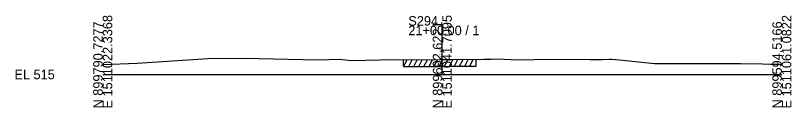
# Model space of a CAD drawing. Extents: x 974 to 2203, y -10 to 19041.
# Drawn here: x 1974.3 to 2202.8, y 1990.3 to 2017.3 of the extents above; entities that cross this region are included whole.
import ezdxf

# ---------------------------------------------------------------- set-up
doc = ezdxf.new("R2010")
doc.units = 0
for name, color, linetype in [('RD_GPK_XS_Cell', 7, 'Continuous'), ('RD_XS_ExGround', 7, 'Continuous'), ('RD_XS_ExPaveRet', 7, 'Continuous'), ('RD_XS_TX_Elev_EX', 7, 'Continuous')]:
    doc.layers.add(name, color=color, linetype=linetype)

msp = doc.modelspace()

# ---------------------------------------------------------------- linework, layer by layer
at = {"layer": 'RD_GPK_XS_Cell'}
for p, q in [((2100, 2000), (2100, 2014.35)), ((2000, 2000), (2100, 2000)), ((2100, 2000), (2200, 2000))]:
    msp.add_line(p, q, dxfattribs=at)
at = {"layer": 'RD_XS_ExGround'}
msp.add_lwpolyline([(2000, 2002.97), (2010.13, 2003.3), (2030.94, 2004.72), (2041.53, 2004.78), (2063.35, 2004.27), (2069.72, 2004.47), (2073.18, 2004.07), (2081.48, 2004.28), (2100, 2004.38), (2102.09, 2004.39), (2102.55, 2004.4), (2112.21, 2004.49), (2114.43, 2004.54), (2116.29, 2004.56), (2122.13, 2004.33), (2132, 2004.46), (2143.56, 2004.4), (2147.2, 2004.43), (2149.11, 2004.55), (2149.82, 2004.52), (2152.19, 2004.32), (2162.46, 2003.26), (2162.95, 2003.22), (2187.79, 2003.21), (2194.34, 2003.14), (2196.67, 2003.06), (2197.12, 2003.05), (2200, 2003.06)], dxfattribs=at)
at = {"layer": 'RD_XS_ExPaveRet'}
for p, q in [((2088.61, 2002.32), (2089.61, 2004.32)), ((2088.61, 2002.32), (2088.61, 2004.32)), ((2090.11, 2002.32), (2091.11, 2004.33)), ((2091.61, 2002.33), (2092.61, 2004.34)), ((2093.11, 2002.34), (2094.11, 2004.35)), ((2094.61, 2002.35), (2095.61, 2004.35)), ((2096.11, 2002.36), (2097.11, 2004.36)), ((2097.61, 2002.37), (2098.61, 2004.37)), ((2099.11, 2002.37), (2100.11, 2004.38)), ((2100.61, 2002.38), (2101.61, 2004.39)), ((2102.11, 2002.39), (2103.12, 2004.4)), ((2103.61, 2002.41), (2104.61, 2004.42)), ((2105.11, 2002.42), (2106.11, 2004.43)), ((2106.61, 2002.44), (2107.61, 2004.44)), ((2108.11, 2002.45), (2109.11, 2004.46)), ((2109.87, 2004.46), (2109.87, 2002.46)), ((2088.61, 2002.32), (2100, 2002.38)), ((2100, 2002.38), (2102.09, 2002.39)), ((2102.09, 2002.39), (2102.55, 2002.4)), ((2102.55, 2002.4), (2109.87, 2002.46))]:
    msp.add_line(p, q, dxfattribs=at)

# ---------------------------------------------------------------- texts
at = {"layer": 'RD_GPK_XS_Cell'}
for s, p in [('E 1511022.3368', (2002.8, 1990)), ('E 1511041.7095', (2102.8, 1990)), ('E 1511061.0822', (2202.8, 1990)), ('N 899790.7277', (2000, 1990)), ('N 899692.6221', (2100, 1990)), ('N 899594.5166', (2200, 1990))]:
    msp.add_text(s, height=2.8, rotation=90, dxfattribs=at).set_placement(p)
for s, p in [('S294', (2090, 2014.35)), ('21+00.00 / 1', (2090, 2011.55)), ('EL 515', (1974, 1998.6))]:
    msp.add_text(s, height=2.8, dxfattribs=at).set_placement(p)
at = {"layer": 'RD_XS_TX_Elev_EX'}
msp.add_text('517.19', height=0.75, rotation=90, dxfattribs=at).set_placement((2100, 2004.38))

doc.saveas('drawing.dxf')
